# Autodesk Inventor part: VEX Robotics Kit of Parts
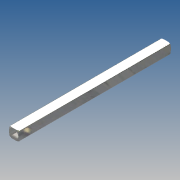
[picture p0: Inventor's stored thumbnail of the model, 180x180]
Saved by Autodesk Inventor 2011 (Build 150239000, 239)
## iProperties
Company: Autodesk Inc.
Created: 2010-06
Document SubType Name: Modeling
Designer: Autodesk Inc.
Density: 1 g/cm^3
Catalog Web Link: http://vexrobotics.com/products
Vendor: Innovation First, Inc.
Author: Autodesk Inc.
Title: VEX Robotics Kit of Parts
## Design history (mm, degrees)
sketch "Sketch1"
  geometry: L1 (0.378, 1.587)-(-0.378, 1.587); L2 (-1.334, 1.587)-(-0.378, 1.587); L3 (-1.588, 0.378)-(-1.588, -0.378); L4 (-0.378, -1.588)-(0.378, -1.588); L5 (-1.587, -1.334)-(-1.588, -0.378); L6 (-0.378, -1.588)-(-1.334, -1.587); L7 (-1.588, 0.378)-(-1.587, 1.334); L8 (1.587, 1.334)-(1.588, 0.378); L9 (0.378, 1.587)-(1.334, 1.587); L10 (1.588, -0.378)-(1.588, 0.378); L11 (1.334, -1.587)-(0.378, -1.588); L12 (1.588, -0.378)-(1.587, -1.334); A1 r 1.632 centre (0, 0) between (-0.378, 1.587) and (-1.588, 0.378); A2 r 1.632 centre (0, 0) between (-0.378, 1.587) and (-1.588, 0.378); A3 r 1.632 centre (0, 0) between (-1.588, -0.378) and (-0.378, -1.588); A4 r 1.632 centre (0, 0) between (-1.588, -0.378) and (-0.378, -1.588); A5 r 1.632 centre (0, 0) between (1.588, 0.378) and (0.378, 1.587); A6 r 1.632 centre (0, 0) between (1.588, 0.378) and (0.378, 1.587); A7 r 1.632 centre (0, 0) between (0.378, -1.588) and (1.588, -0.378); A8 r 1.632 centre (0, 0) between (0.378, -1.588) and (1.588, -0.378); 1 further point
  constraints: 24 end point, 16 point on circle, 8 centre point, 8 other
extrude "Extrusion1" new body sketch "Sketch1" distance "d0" = 50.8; taper "d1" = 0 deg
workplane "Work Plane1"
  workaxis "Work Axis1"
sketch "Sketch2"
  geometry: L1 (0, 0)-(0.352, 0); L2 (0.352, 0)-(0.352, 2.14); L3 (0.352, 2.14)-(-0.254, 2.14); L4 (0, 0)-(0, 1.39); L5 (-61.03, 0)-(10.582, 0) reference; A1 r 0.772 centre (-0.757, 1.554) between (-0.179, 2.065) and (-0.254, 2.14); 1 further point
  constraints: 8 end point, 2 perpendicular, 2 point on circle, 1 centre point, 3 other
revolve "Revolution1" sketch "Sketch2" stored, may be unused: angle "d3" = 90 deg
workplane "Work Plane2"
mirror "Mirror1"
body "Solid1"
other parameters: "d2" = 90 deg
